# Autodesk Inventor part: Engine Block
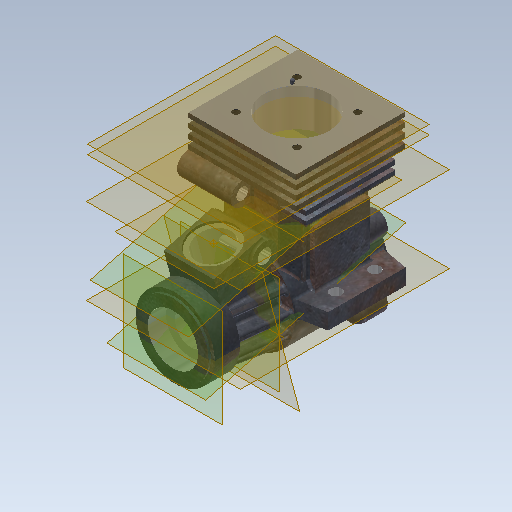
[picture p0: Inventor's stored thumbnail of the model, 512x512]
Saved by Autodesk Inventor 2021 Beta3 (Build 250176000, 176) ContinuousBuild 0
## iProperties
Created: 2012-08
Part Number: Engine Block
Material: Aluminum 6061
Document SubType Name: Modeling
Designer: John
Density: 2.71 g/cm^3
Mass: 63.8381 g
Surface Area: 180.199 cm^2
Volume: 23.5565 cm^3
Appearance: Oxidized
Author: John
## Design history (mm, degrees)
sketch "Sketch2"
  geometry: C1 r 12.509 at (0, 0); 1 further point
  constraints: 1 centre point, 1 coincident
  dimensions: "d0" = 25.019 diameter of C1
extrude "Extrusion1" new body sketch "Sketch2" distance "d1" = 26.162; taper "d2" = 0 deg
workplane "Work Plane1"
sketch "Sketch6"
  geometry: C1 r 11.049 at (0, 0); 1 further point
  constraints: 1 centre point, 1 coincident
  dimensions: "d15" = 22.098 diameter of C1
extrude "Extrusion4" join sketch "Sketch6" distance "d16" = 7.62; taper "d17" = 0 deg
sketch "Sketch8"
  geometry: C1 r 11.049 at (0, 0) reference; C2 r 7.239 at (0, 0)
  constraints: 1 centre point, 1 coincident
  dimensions: "d50" = 22.098 diameter of C1 (derived); "d55" = 7.239 radius of C2
sketch "Sketch9"
  geometry: C1 r 12.509 at (0, 0) reference; C2 r 8.712 at (0, 0)
  constraints: 1 centre point, 1 coincident
  dimensions: "d29" = 8.7122 radius of C2
loft "Loft2" sketch "Sketch8", "Sketch9" dims "d30" = 0, "d31" = 90 deg, "d32" = 0, "d33" = 90 deg
sketch "Sketch10"
  geometry: C1 r 11.049 at (0, 0) reference; C2 r 10.414 at (0, 0)
  constraints: 1 centre point, 1 coincident
  dimensions: "d34" = 10.414 radius of C2
sketch "Sketch11"
  geometry: C1 r 12.509 at (0, 0) reference; C2 r 11.887 at (0, 0)
  constraints: 1 centre point, 1 coincident
  dimensions: "d35" = 11.8872 radius of C2
feature "LoftSrf1" sketch "Sketch10", "Sketch11" dims "d36" = 0, "d37" = 90 deg, "d38" = 0, "d39" = 90 deg
sketch "Sketch7"
  geometry: L1 (40.005, 11.049)-(40.005, -11.049) reference; L2 (26.162, -12.509)-(26.162, 12.509) reference; L3 (40.005, 0)-(26.162, 0); L4 (26.162, 0)-(26.162, 1.905); L5 (26.162, 1.905)-(40.005, 1.905); L6 (40.005, 1.905)-(40.005, 0); L7 (40.005, -5.08)-(26.162, -5.08); L8 (26.162, -5.08)-(26.162, -3.175); L9 (26.162, -3.175)-(40.005, -3.175); L10 (40.005, -3.175)-(40.005, -5.08); L11 (40.005, 5.08)-(26.162, 5.08); L12 (26.162, 5.08)-(26.162, 6.985); L13 (26.162, 6.985)-(40.005, 6.985); L14 (40.005, 6.985)-(40.005, 5.08); L15 (40.005, 10.16)-(26.162, 10.16); L16 (40.005, -10.16)-(26.162, -10.16); L17 (26.162, -10.16)-(26.162, -8.255); L18 (26.162, -8.255)-(40.005, -8.255); L19 (40.005, -8.255)-(40.005, -10.16); 1 further point
  constraints: 34 end point, 9 point on line, 8 parallel, 5 perpendicular, 4 horizontal, 1 midpoint
  dimensions: "d18" = 5.08 distance between parallel lines of L7 L3; "d20" = 3.175 distance between parallel lines of L3 L9; "d21" = 5.08 distance between parallel lines of L11 L3 (= d18); "d22" = 3.175 distance between parallel lines of L11 L5 (= d20); "d23" = 5.08 distance between parallel lines of L11 L15 (= d21); "d24" = 3.175 distance between parallel lines of L13 L15 (= d20); "d25" = 5.08 distance between parallel lines of L7 L16 (= d18); "d26" = 3.175 distance between parallel lines of L7 L18 (= d20)
extrude "Extrusion5" join sketch "Sketch7" stored distance "d40" = 25.019 (= d0); taper "d41" = 0 deg
mirror "Mirror1"
sketch "Sketch12"
  geometry: L1 (0, 0)-(0, 12.342) reference; L2 (13.843, 8.457)-(13.843, 3.885) reference; L3 (0, 6.171)-(13.843, 6.171); L4 (0, 6.171)-(13.843, 6.171); L5 (13.843, 6.171)-(13.843, 7.441); L6 (13.843, 7.441)-(0, 7.441); L7 (0, 7.441)-(0, 6.171); L8 (0, 6.171)-(13.843, 6.171); L9 (13.843, 6.171)-(13.843, 4.901); L10 (13.843, 4.901)-(0, 4.901); L11 (0, 4.901)-(0, 6.171); 1 further point
  constraints: 18 end point, 4 parallel, 3 horizontal, 2 midpoint, 2 perpendicular, 2 point on line
  dimensions: "d42" = 1.27 distance of L5.end L4.end; "d43" = 1.27 distance between parallel lines of L8 L10 (= d42)
extrude "Extrusion6" join sketch "Sketch12" stored distance "d44" = 6.5278; taper "d45" = 0 deg
workaxis "Work Axis1"
  workplane "Work Plane2"
workplane "Work Plane3"
workpoint "Work Point1"
  workplane "Work Plane5"
  workplane "Work Plane6"
sketch "Sketch13"
  geometry: L1 (-6.985, -17.642)-(6.985, -17.642); L2 (6.985, -17.642)-(6.985, -3.672); L3 (6.985, -3.672)-(-6.985, -3.672); L4 (-6.985, -3.672)-(-6.985, -17.642); L5 (-6.985, -17.642)-(6.985, -3.672); L6 (6.985, -17.642)-(-6.985, -3.672); 2 further points
  constraints: 12 end point, 2 midpoint, 2 parallel, 1 horizontal, 1 perpendicular
  dimensions: "d63" = 13.97 distance of L3.end L2.end; "d64" = 13.97 distance of L2.end L1.end
extrude "Extrusion7" join sketch "Sketch13" stored distance "d65" = 6.5278; taper "d66" = 0 deg
sketch "Sketch14"
  geometry: L1 (9.093, -9.093)-(-9.093, -9.093); L2 (-9.093, -9.093)-(-9.093, 9.093); L3 (-9.093, 9.093)-(9.093, 9.093); L4 (9.093, 9.093)-(9.093, -9.093); L5 (9.093, -9.093)-(-9.093, 9.093); L6 (-9.093, -9.093)-(9.093, 9.093); C1 r 12.509 at (0, 0) reference; C2 r 3.175 at (-9.093, 9.093); C3 r 3.175 at (-9.093, -9.093); C4 r 3.175 at (9.093, -9.093); C5 r 3.175 at (9.093, 9.093)
  constraints: 12 end point, 4 centre point, 4 coincident, 3 equal radius, 2 midpoint, 2 parallel, 1 horizontal, 1 perpendicular
  dimensions: "d67" = 18.1864 distance of L2.end L3.end; "d68" = 18.1864 distance of L1.end L2.end (= d67); "d69" = 3.175 radius of C2
extrude "Extrusion8" join sketch "Sketch14" distance "d70" = 8.128; taper "d71" = 0 deg
sketch "Sketch15"
  geometry: A1 r 3.175 centre (-9.093, 9.093) between (-6.388, 10.755) and (-10.755, 6.388) reference; A2 r 3.175 centre (-9.093, -9.093) between (-10.755, -6.388) and (-6.388, -10.755) reference; A3 r 3.175 centre (9.093, -9.093) between (6.388, -10.755) and (10.755, -6.388) reference; A4 r 3.175 centre (9.093, 9.093) between (10.755, 6.388) and (6.388, 10.755) reference
hole "Hole1" sketch "Sketch15" at (-9.093, -9.093), (-9.093, 9.093), (9.093, 9.093), (9.093, -9.093) diameter "d72" = 1.9304; stored, may be unused: countersink angle "d76" = 82 deg, drill point angle "d78" = 118 deg; dims "d73" = 5.08, "d74" = 9.525, "d75" = 6.35, "d77" = 5.715
fillet "Fillet1" dims "d79" = 5.08
sketch "Sketch16"
  geometry: L1 (-26.162, 12.509)-(-26.162, -12.509) reference; L2 (-8.128, -4.073)-(-8.128, -10.755) reference; L3 (0, 4.073)-(-8.128, 4.073) reference; L4 (0, 4.073)-(0, -4.073) reference; L5 (-8.128, -4.073)-(0, -4.073) reference; L6 (0, 10.755)-(0, 10.755) reference; L7 (0, -4.073)-(-8.128, -4.073) reference; L8 (0, -4.073)-(0, 4.073) reference; L9 (-8.128, 4.073)-(0, 4.073) reference; L10 (0, 12.509)-(-26.162, 12.509) reference; L11 (0, -12.509)-(-26.162, -12.509) reference; L12 (-25.146, -12.509)-(-23.876, -19.495); L13 (-23.876, -19.495)-(-2.286, -19.495); L14 (-2.286, -19.495)-(-1.016, -12.509); L15 (-13.081, -12.509)-(-13.081, -20.281); L16 (0, 0)-(14.217, 0); L17 (-25.146, -12.509)-(-26.162, -6.921); L18 (-1.016, -12.509)-(0, -6.922); L19 (0, -7.799)-(0, -4.073) reference; L20 (0, -8.128)-(0, -10.058) reference; L21 (0, -7.799)-(0, -12.268) reference; L22 (0, -6.922)-(-26.162, -6.921); L23 (-8.128, -10.755)-(0, -10.755) reference; L24 (0, -10.755)-(-8.128, -10.755) reference; L25 (-8.128, -10.755)-(-8.128, -4.073) reference; L26 (-8.128, 4.073)-(-8.128, 10.755) reference; L27 (-8.128, 10.755)-(0, 10.755) reference; L28 (0, 10.755)-(-8.128, 10.755) reference; L29 (-8.128, 10.755)-(-8.128, 4.073) reference; L30 (0, -10.755)-(0, -10.755) reference; 3 further points
  constraints: 16 end point, 4 point on line, 3 perpendicular, 2 collinear, 1 midpoint, 1 parallel, 1 other
  dimensions: "d80" = 21.59 distance of L12.end L13.end; "d82" = 24.13 distance of L14.end L12.start; "d83" = 38.989 diameter of L13 L16
extrude "Extrusion9" join sketch "Sketch16" distance "d84" = 4.445; taper "d85" = 0 deg
sketch "Sketch17"
  geometry: L1 (-23.876, -19.495)-(-2.286, -19.495) reference; L2 (-17.886, -15.685)-(-7.091, -15.685); L3 (-12.488, -15.685)-(-12.488, -19.495); 1 further point
  constraints: 4 end point, 1 horizontal alignment, 1 midpoint, 1 parallel, 1 point on line, 1 vertical
  dimensions: "d86" = 3.81 distance from line of L2.end L1; "d87" = 10.795 distance of L2.end L2.start
hole "Hole2" sketch "Sketch17" at (-17.886, -15.685), (-7.091, -15.685) diameter "d88" = 3.175; stored, may be unused: countersink angle "d92" = 82 deg, drill point angle "d94" = 118 deg; dims "d89" = 5.08, "d90" = 9.525, "d91" = 6.35, "d93" = 5.715
mirror "Mirror2"
workplane "Work Plane7"
sketch "Sketch18"
  geometry: L1 (0, 10.058)-(0, 8.128) reference; L2 (0, -8.128)-(0, -10.058) reference; L3 (0, 10.058)-(0, 8.128) reference; L4 (0, -8.128)-(0, -10.058) reference; L5 (0, 7.799)-(0, 10.755) reference; L6 (0, 4.073)-(0, 7.799) reference; L7 (0, -4.073)-(0, 4.073) reference; L8 (0, -7.799)-(0, -4.073) reference; L9 (0, -10.755)-(0, -7.799) reference; L10 (0, 10.755)-(0, 10.755) reference; L11 (0, -7.799)-(0, -10.755) reference; L12 (0, -4.073)-(0, -7.799) reference; L13 (0, 4.073)-(0, -4.073) reference; L14 (0, 7.799)-(0, 4.073) reference; L15 (0, 10.755)-(0, 7.799) reference; L16 (-57.15, 0)-(9.525, 0) reference; L17 (-0.635, -10.668)-(-25.527, -10.668); L18 (-25.527, -10.668)-(-25.527, 10.668); L19 (-25.527, 10.668)-(-0.635, 10.668); L20 (-0.635, 10.668)-(-0.635, -10.668); L21 (0, -10.755)-(0, -10.755) reference; 1 further point
  constraints: 8 end point, 2 parallel, 1 horizontal, 1 perpendicular
  dimensions: "d96" = 0.635 distance between parallel lines of L6 L20; "d97" = 24.892 distance of L17.start L17.end; "d98" = 21.336 distance of L19.end L17.start; "d99" = 10.668 distance between parallel lines of L16 L17 (= 0.5 x d98)
extrude "Extrusion10" join sketch "Sketch18" stored distance "d100" = 4.445; taper "d101" = 0 deg
sketch "Sketch19"
  geometry: L1 (23.876, 4.445)-(2.286, 4.445) reference; L2 (13.081, 4.445)-(13.081, 19.685); L3 (5.461, 4.445)-(20.701, 4.445); L4 (20.701, 4.445)-(20.701, 19.685); L5 (20.701, 19.685)-(5.461, 19.685); L6 (5.461, 19.685)-(5.461, 4.445); 1 further point
  constraints: 10 end point, 2 midpoint, 2 parallel, 2 perpendicular, 1 horizontal, 1 point on line
  dimensions: "d102" = 15.24 distance of L2.end L2.start; "d103" = 15.24 distance of L4.end L5.end (= d102)
extrude "Extrusion11" join sketch "Sketch19" stored distance "d104" = 25.4; taper "d105" = 0 deg
chamfer "Chamfer1" distance "d106" = 3.175; stored, may be unused: second distance "d107" = 3.175, angle "d108" = 45 deg
sketch "Sketch20"
  geometry: L1 (-22.352, 10.668)-(-3.81, 10.668) reference; L2 (-25.527, -7.493)-(-25.527, 7.493) reference; L3 (-3.81, -10.668)-(-22.352, -10.668) reference; L4 (-0.635, 7.493)-(-0.635, -7.493) reference; L5 (-13.081, 10.668)-(-13.081, -10.668); L6 (-0.635, 0)-(-25.527, 0); L7 (-28.321, -14.986)-(2.159, -14.986); L8 (2.159, -14.986)-(2.159, 14.986); L9 (2.159, 14.986)-(-28.321, 14.986); L10 (-28.321, 14.986)-(-28.321, -14.986); L11 (-28.321, -14.986)-(2.159, 14.986); L12 (2.159, -14.986)-(-28.321, 14.986); 2 further points
  constraints: 16 end point, 7 midpoint, 2 parallel, 1 horizontal, 1 perpendicular
  dimensions: "d109" = 30.48 distance of L9.end L8.end; "d110" = 29.972 distance of L9.end L7.start
extrude "Extrusion12" join sketch "Sketch20" distance "d111" = 15.24; taper "d112" = 0 deg
workplane "Work Plane8"
sketch "Sketch21"
  geometry: L1 (2.159, -14.986)-(-28.321, -14.986) reference; L2 (-28.321, -14.986)-(-28.321, 14.986) reference; L3 (-28.321, 14.986)-(2.159, 14.986) reference; L4 (2.159, 14.986)-(2.159, -14.986) reference; L5 (-22.352, -10.668)-(-25.527, -7.493) reference; L6 (-3.81, -10.668)-(-22.352, -10.668) reference; L7 (-0.635, -7.493)-(-3.81, -10.668) reference; L8 (-0.635, 7.493)-(-0.635, -7.493) reference; L9 (-3.81, 10.668)-(-0.635, 7.493) reference; L10 (-22.352, 10.668)-(-3.81, 10.668) reference; L11 (-25.527, 7.493)-(-22.352, 10.668) reference; L12 (-25.527, -7.493)-(-25.527, 7.493) reference; L13 (-4.191, 8.636)-(-21.971, 8.636); L14 (-21.971, 8.636)-(-21.971, -8.636); L15 (-21.971, -8.636)-(-4.191, -8.636); L16 (-4.191, -8.636)-(-4.191, 8.636); 1 further point
  constraints: 8 end point, 3 other
  dimensions: "d114" = 6.35 distance between parallel lines of L3 L13
extrude "Extrusion13" cut sketch "Sketch21" distance "d115" = 1.27; taper "d116" = 0 deg
pattern_linear "Rectangular Pattern1" dims "d119" = 2.54
sketch "Sketch22"
  geometry: L1 (30.48, 8.89)-(0, 8.89) reference; L2 (0, 7.62)-(0, 8.89) reference; L3 (0, 7.62)-(30.48, 7.62) reference; L4 (30.48, 7.62)-(30.48, 8.89) reference; L5 (30.48, 15.24)-(0, 15.24); A1 r 3.175 centre (30.48, 12.065) between (30.48, 8.89) and (30.48, 15.24); A2 r 3.175 centre (0, 12.065) between (0, 15.24) and (0, 8.89); 1 further point
  constraints: 4 point on circle, 4 tangent, 2 centre point, 2 end point, 1 perpendicular
  dimensions: "d120" = 3.175 radius of A2
extrude "Extrusion14" join sketch "Sketch22" stored distance "d122" = 1.27; taper "d123" = 0 deg
sketch "Sketch23"
  geometry: L1 (0, 0)-(0, 1.27) reference; L2 (2.794, 0)-(0, 0) reference; L3 (2.794, -1.27)-(2.794, 0) reference; L4 (0, -1.27)-(2.794, -1.27) reference; L5 (0, -2.54)-(0, -1.27) reference; L6 (2.794, -2.54)-(0, -2.54) reference; L7 (2.794, -3.81)-(2.794, -2.54) reference; L8 (0, -3.81)-(2.794, -3.81) reference; L9 (0, -5.08)-(0, -3.81) reference; L10 (0, -5.08)-(2.794, -5.08) reference; L11 (0, 1.27)-(2.794, 1.27) reference; L12 (-24.892, 1.27)-(-24.892, 0) reference; L13 (-27.686, 1.27)-(-24.892, 1.27) reference; L14 (-27.686, -5.08)-(-24.892, -5.08) reference; L15 (-24.892, -3.81)-(-24.892, -5.08) reference; L16 (-27.686, -3.81)-(-24.892, -3.81) reference; L17 (-27.686, -2.54)-(-27.686, -3.81) reference; L18 (-24.892, -2.54)-(-27.686, -2.54) reference; L19 (-24.892, -1.27)-(-24.892, -2.54) reference; L20 (-27.686, -1.27)-(-24.892, -1.27) reference; L21 (-27.686, 0)-(-27.686, -1.27) reference; L22 (-24.892, 0)-(-27.686, 0) reference; L23 (-24.892, 0)-(-24.892, -1.27); L24 (-24.892, -2.54)-(-24.892, -3.81); L25 (0, 0)-(0, -1.27); L26 (0, -2.54)-(0, -3.81); A1 r 3.175 centre (2.794, -1.905) between (2.794, -5.08) and (2.794, 1.27) reference; A2 r 3.175 centre (-27.686, -1.905) between (-27.686, 1.27) and (-27.686, -5.08) reference; 1 further point
  constraints: 8 end point, 3 equal length, 1 perpendicular
extrude "Extrusion15" cut sketch "Sketch23" extent not by distance; stored distance "d124" = 0; taper "d125" = 0 deg
sketch "Sketch24"
  geometry: A1 r 12.509 centre (0, 0) between (6.388, 10.755) and (-6.388, 10.755) reference
hole "Hole3" sketch "Sketch24" at (0, 0) diameter "d126" = 20.955; stored, may be unused: countersink angle "d130" = 82 deg, drill point angle "d132" = 0 deg; dims "d127" = 5.08, "d128" = 9.525, "d129" = 6.35, "d131" = 19.685
sketch "Sketch25"
  geometry: L1 (-28.321, -14.986)-(2.159, 14.986); L2 (-21.565, -8.484)-(-4.597, -8.484); L3 (-4.597, -8.484)-(-4.597, 8.484); L4 (-4.597, 8.484)-(-21.565, 8.484); L5 (-21.565, 8.484)-(-21.565, -8.484); L6 (-21.565, -8.484)-(-4.597, 8.484); L7 (-4.597, -8.484)-(-21.565, 8.484); 2 further points
  constraints: 14 end point, 3 midpoint, 2 parallel, 1 horizontal, 1 perpendicular
  dimensions: "d228" = 16.9672 distance of L4.end L3.end; "d229" = 16.9672 distance of L2.end L3.end (= d228)
hole "Hole14" sketch "Sketch25" at (-21.565, 8.484), (-4.597, 8.484), (-4.597, -8.484), (-21.565, -8.484) diameter "d230" = 1.9304; stored, may be unused: countersink angle "d234" = 82 deg, drill point angle "d236" = 118 deg; dims "d231" = 19.05, "d232" = 3.0226, "d233" = 6.35, "d235" = 7.62
sketch "Sketch26"
  geometry: L1 (-21.565, -8.484)-(-4.597, 8.484); C1 r 0.965 at (-4.597, 8.484) reference; C2 r 0.965 at (-21.565, -8.484) reference; 2 further points
  constraints: 2 end point, 1 midpoint
hole "Hole5" sketch "Sketch26" at (-13.081, 0) diameter "d142" = 18.034; stored, may be unused: countersink angle "d146" = 82 deg, drill point angle "d148" = 118 deg; dims "d143" = 18.034, "d144" = 9.525, "d145" = 6.35, "d147" = 27.559
sketch "Sketch27"
  geometry: C1 r 11.049 at (0, 0) reference; C2 r 9.97 at (0, 0)
  constraints: 1 centre point, 1 coincident
  dimensions: "d150" = 19.939 diameter of C2
extrude "Extrusion16" cut sketch "Sketch27" distance "d152" = 0.635; taper "d153" = 0 deg
sketch "Sketch28"
  geometry: C1 r 9.97 at (0, 0) reference
hole "Hole6" sketch "Sketch28" at (0, 0) diameter "d154" = 13.97; stored, may be unused: countersink angle "d158" = 82 deg, drill point angle "d160" = 0 deg; dims "d155" = 18.034, "d156" = 9.525, "d157" = 6.35, "d159" = 5.08
sketch "Sketch29"
  geometry: A1 r 10.477 centre (0, 0) between (-9.436, -4.555) and (-9.436, 4.555) reference
hole "Hole7" sketch "Sketch29" at (0, 0) diameter "d161" = 13.97; stored, may be unused: countersink angle "d165" = 82 deg, drill point angle "d167" = 0 deg; dims "d162" = 18.034, "d163" = 9.525, "d164" = 6.35, "d166" = 5.08
sketch "Sketch30"
  geometry: C1 r 6.985 at (0, 0) reference
hole "Hole8" sketch "Sketch30" at (0, 0) diameter "d168" = 9.017; stored, may be unused: countersink angle "d172" = 82 deg, drill point angle "d174" = 0 deg; dims "d169" = 18.034, "d170" = 9.525, "d171" = 6.35, "d173" = 5.08
sketch "Sketch31"
  geometry: L1 (0, 0)-(0, 1.576) reference; L2 (10.296, 12.385)-(10.296, 7.94); C1 r 3.493 at (10.296, 7.94); 1 further point
  constraints: 2 end point, 1 centre point, 1 coincident, 1 parallel
  dimensions: "d175" = 4.445 distance of L2.start L2.end; "d177" = 6.985 diameter of C1
extrude "Extrusion17" join sketch "Sketch31" stored distance "d178" = 0.635; taper "d179" = 0 deg
sketch "Sketch32"
  geometry: A1 r 3.493 centre (10.296, 7.94) between (12.261, 5.052) and (10.554, 11.423) reference; 2 further points
  constraints: 1 coincident, 3 other
extrude "Extrusion18" join sketch "Sketch32" distance "d180" = 0.635; taper "d181" = 0 deg
sketch "Sketch33"
  geometry: A1 r 3.493 centre (10.296, -7.94) between (10.554, -11.423) and (12.261, -5.052) reference; 2 further points
  constraints: 1 coincident, 3 other
extrude "Extrusion19" join sketch "Sketch33" distance "d182" = 0.635; taper "d183" = 0 deg
sketch "Sketch34"
  geometry: C1 r 3.492 at (0, 0) reference; 1 further point
hole "Hole9" sketch "Sketch34" at (0, 0) diameter "d184" = 3.937; stored, may be unused: countersink angle "d188" = 82 deg, drill point angle "d190" = 0 deg; dims "d185" = 18.034, "d186" = 9.525, "d187" = 6.35, "d189" = 5.08
sketch "Sketch35"
  geometry: A1 r 3.175 centre (30.48, 4.445) between (30.48, 1.27) and (30.48, 7.62) reference; A2 r 3.175 centre (0, 4.445) between (0, 7.62) and (0, 1.27) reference; 1 further point
hole "Hole10" sketch "Sketch35" at (0, 4.445), (30.48, 4.445) diameter "d191" = 3.2766; stored, may be unused: countersink angle "d195" = 82 deg, drill point angle "d197" = 0 deg; dims "d192" = 18.034, "d193" = 9.525, "d194" = 6.35, "d196" = 5.08
workplane "Work Plane9"
sketch "Sketch38"
  geometry: L1 (-3.672, -6.985)-(-17.642, 6.985); 2 further points
  constraints: 2 end point, 1 midpoint
hole "Hole11" sketch "Sketch38" at (-10.657, 0) diameter "d202" = 12.446; stored, may be unused: countersink angle "d206" = 82 deg, drill point angle "d208" = 0 deg; dims "d203" = 18.034, "d204" = 9.525, "d205" = 6.35, "d207" = 0.762
sketch "Sketch39"
  geometry: C1 r 6.223 at (0, 0) reference; 2 further points
  constraints: 1 coincident
hole "Hole12" sketch "Sketch39" at (0, 0) diameter "d209" = 9.9568; stored, may be unused: countersink angle "d213" = 82 deg, drill point angle "d215" = 0 deg; dims "d210" = 18.034, "d211" = 9.525, "d212" = 6.35, "d214" = 9.525
sketch "Sketch40"
  geometry: C1 r 4.978 at (0, 0) reference; 2 further points
  constraints: 1 coincident
hole "Hole13" sketch "Sketch40" at (0, 0) diameter "d216" = 8.89; stored, may be unused: countersink angle "d220" = 82 deg, drill point angle "d222" = 0 deg; dims "d217" = 18.034, "d218" = 9.525, "d219" = 6.35, "d221" = 9.525
sketch "Sketch37"
  geometry: L1 (0, 82.674)-(-30.48, 82.674) reference; L2 (-6.223, 67.688)-(-6.223, 82.674); L3 (-15.24, 67.688)-(-15.24, 76.705); L4 (-15.24, 76.705)-(-24.089, 82.674); A1 r 9.017 centre (-15.24, 67.688) between (-6.744, 70.707) and (-6.744, 64.668) reference; A2 r 9.017 centre (-15.24, 67.688) between (-6.744, 70.707) and (-6.223, 67.688); 1 further point
  constraints: 6 end point, 4 point on circle, 2 point on line, 1 centre point, 1 coincident, 1 parallel, 1 perpendicular, 1 tangent
  dimensions: "d199" = 56 deg angle of L3 L4
extrude "Extrusion20" cut sketch "Sketch37" distance "d200" = 3.175; taper "d201" = 0 deg
sketch "Sketch41"
  geometry: C1 r 9.017 at (-13.081, 0) reference; C2 r 0.508 at (-6.731, 7.62); 1 further point
  constraints: 1 centre point
  dimensions: "d223" = 6.35 horizontal distance of C1.centre C2.centre; "d224" = 1.016 diameter of C2; "d225" = 7.62 vertical distance of C2.centre C1.centre
extrude "Extrusion21" join sketch "Sketch41" distance "d226" = 0.889; taper "d227" = 0 deg
fillet "Fillet2" dims "d237" = 0.635
fillet "Fillet3" dims "d238" = 2.54
fillet "Fillet4" dims "d239" = 0.508
fillet "Fillet6" dims "d241" = 3.175
fillet "Fillet5" dims "d240" = 0.635
body "Solid1"
body "Srf1"
workplane "Work Plane4"
workaxis "Work Axis2"
node "Projected Loop1"
node "Projected Loop2"
node "Projected Loop3"
node "Projected Loop4"
node "Projected Loop5"
other parameters: "d14" = -47.625, "d53" = 12.5095 (derived), "d58" = 15.875, "d59" = 165 deg, "d60" = 20.32, "d61" = 0, "d62" = 90 deg, "d95" = 37.592, "d113" = -2.54
